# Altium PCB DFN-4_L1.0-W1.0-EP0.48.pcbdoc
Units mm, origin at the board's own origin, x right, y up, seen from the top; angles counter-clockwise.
Board outline 14.08 x 13.76 mm, 2 copper layers (Top Layer, Bottom Layer), stack 0 mm thick; 1 components, 0 nets, 5 pads, 0 vias.
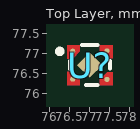
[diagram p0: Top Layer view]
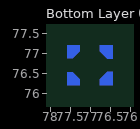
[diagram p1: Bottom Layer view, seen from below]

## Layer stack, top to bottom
Top Layer: signal copper (thickness not stored)
Bottom Layer: signal copper (thickness not stored)

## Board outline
83.93,69.85 69.85,69.85 69.85,83.612 83.93,83.612

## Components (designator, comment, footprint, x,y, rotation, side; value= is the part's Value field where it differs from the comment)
U? "" DFN-4_L1.0-W1.0-EP0.48 77.01,76.702 r0 top

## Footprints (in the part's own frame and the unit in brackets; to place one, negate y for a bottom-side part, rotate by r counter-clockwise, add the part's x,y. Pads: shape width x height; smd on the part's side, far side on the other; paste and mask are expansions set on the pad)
DFN-4_L1.0-W1.0-EP0.48 [mm]
  round 0.129 smd: 1(-0.428,0.347) 2(-0.428,-0.352) 3(0.428,-0.357) 4(0.428,0.357)
  rect 0.45x0.45 smd rot 45 paste+0 mask+0.05: 5(0,0.003)
  Top Layer region: -0.25,0.493 -0.25,0.353 -0.25,0.343 -0.43,0.163 -0.57,0.163 -0.57,0.493
  Top Layer region: -0.25,-0.497 -0.25,-0.358 -0.25,-0.347 -0.43,-0.168 -0.57,-0.168 -0.57,-0.497
  Top Layer region: 0.25,-0.502 0.25,-0.363 0.25,-0.352 0.43,-0.172 0.57,-0.173 0.57,-0.502
  Top Layer region: 0.25,0.503 0.25,0.363 0.25,0.353 0.43,0.173 0.57,0.173 0.57,0.503
  Bottom Layer region: -0.25,0.493 -0.25,0.353 -0.25,0.343 -0.43,0.163 -0.57,0.163 -0.57,0.493
  Bottom Layer region: -0.25,-0.497 -0.25,-0.358 -0.25,-0.347 -0.43,-0.168 -0.57,-0.168 -0.57,-0.497
  Bottom Layer region: 0.25,-0.502 0.25,-0.363 0.25,-0.352 0.43,-0.172 0.57,-0.173 0.57,-0.502
  Bottom Layer region: 0.25,0.503 0.25,0.363 0.25,0.353 0.43,0.173 0.57,0.173 0.57,0.503
  Multi-Layer region: -0.25,0.493 -0.25,0.353 -0.25,0.343 -0.43,0.163 -0.57,0.163 -0.57,0.493
  Multi-Layer region: -0.25,-0.497 -0.25,-0.358 -0.25,-0.347 -0.43,-0.168 -0.57,-0.168 -0.57,-0.497
  Multi-Layer region: 0.25,-0.502 0.25,-0.363 0.25,-0.352 0.43,-0.172 0.57,-0.173 0.57,-0.502
  Multi-Layer region: 0.25,0.503 0.25,0.363 0.25,0.353 0.43,0.173 0.57,0.173 0.57,0.503
  silkscreen extent -0.81,-0.5 0.51,0.5

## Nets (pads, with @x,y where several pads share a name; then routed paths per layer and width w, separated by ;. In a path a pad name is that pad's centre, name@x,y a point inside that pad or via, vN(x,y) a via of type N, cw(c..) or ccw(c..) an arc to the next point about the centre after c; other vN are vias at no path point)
pads on no net: U?.1 U?.2 U?.3 U?.4 U?.5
